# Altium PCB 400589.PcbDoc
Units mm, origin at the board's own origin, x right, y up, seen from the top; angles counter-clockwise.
Board outline 10.16 x 10.16 mm, 2 copper layers (Top Layer, Bottom Layer); 19 components, 14 nets, 51 pads, 50 vias.
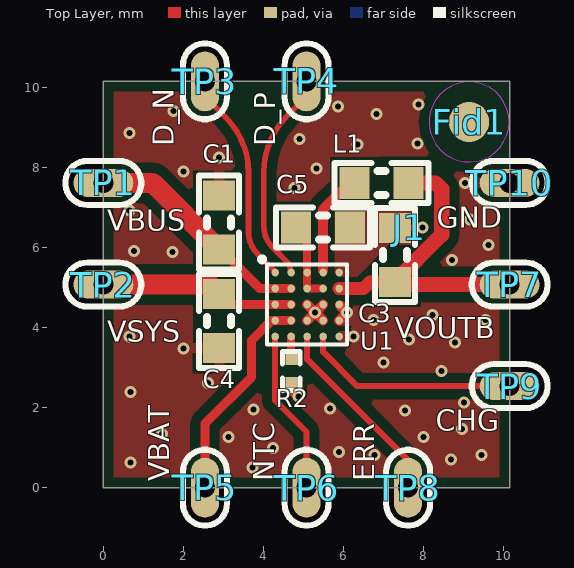
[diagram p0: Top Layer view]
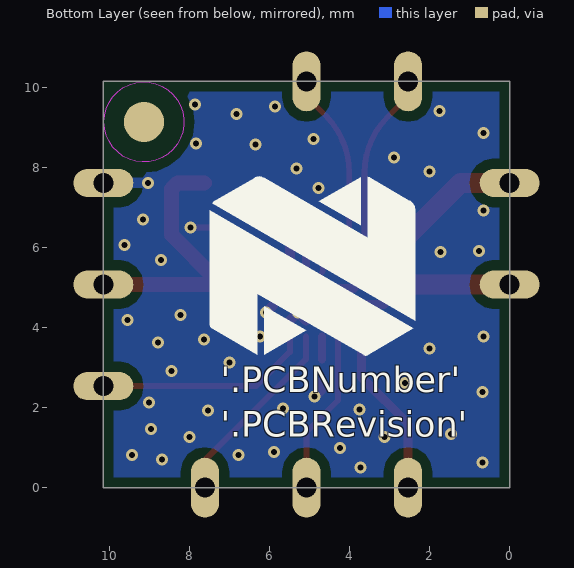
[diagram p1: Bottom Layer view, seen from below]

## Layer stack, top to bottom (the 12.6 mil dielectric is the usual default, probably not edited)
Top Solder: solder mask 0.01, Solder Resist, Dk 3.5
Top Layer: signal copper 0.036
Dielectric1: core 0.32, FR-4, Dk 4.8
Bottom Layer: signal copper 0.036
Bottom Solder: solder mask 0.01, Solder Resist, Dk 3.5

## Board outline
0,0 10.16,0 10.16,10.16 0,10.16

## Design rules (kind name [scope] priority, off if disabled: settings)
BoardOutlineClearance [All] p1: gap=0.254 ignorepadtopadclearanceinfootprint=FALSE except(0: Arc-SplitContinuation Track-SplitContinuation SMDPad-SplitContinuation THPad-SplitContinuation Via-SplitContinuation Fill-SplitContinuation Poly-SplitContinuation Region-SplitContinuation Text-SplitContinuation)
Clearance Clearance_microvia [AsMM(ViaDiameter) = 0.3 vs AsMM(ViaDiameter) = 0.3] p1: gap=0.1 ignorepadtopadclearanceinfootprint=FALSE except(0: Arc-Hole Track-Hole SMDPad-Hole THPad-Hole Via-Hole Fill-Hole Poly-Hole Region-Hole Text-Hole)
Clearance ANT_Clerance [InNet('ANT')] p2: gap=0.127 ignorepadtopadclearanceinfootprint=FALSE except(0: Arc-Hole Track-Hole SMDPad-Hole THPad-Hole Via-Hole Fill-Hole Poly-Hole Region-Hole Text-Hole)
Clearance Polygon_Clearance [(InNamedPolygon('Top_Layer-GND')) or (InNamedPolygon('Bottom_Layer-GND')) or (InNamedPolygon('Mid_Layer_1-GND')) or (InNamedPolygon('Mid_Layer_2-GND'))] p3: gap=0.254 ignorepadtopadclearanceinfootprint=FALSE except(0: Arc-Hole Track-Hole SMDPad-Hole THPad-Hole Via-Hole Fill-Hole Poly-Hole Region-Hole Text-Hole)
Clearance [All] p4: gap=0.125 ignorepadtopadclearanceinfootprint=FALSE
ComponentClearance [All] p1 off: gap=0.254 collisioncheckmode=3 verticalgap=0.254 showdistances=FALSE
DiffPairsRouting [All] p1: maxlimit=0.254 minlimit=0.241 mostfreqgap=0.241 toplayer_minwidth=0.14 toplayer_maxwidth=0.381 toplayer_prefwidth=0.14 bottomlayer_minwidth=0.14 bottomlayer_maxwidth=0.381 bottomlayer_prefwidth=0.14 maxuncoupledlength=12.7
FabricationTestPointUsage TestPointUsage [All] p1: valid=0 allowmultiple=FALSE
FabricationTestpoint Testpoint [All] p1: side=3 testpointundercomponent=TRUE minsize=1.016 maxsize=2.54 preferedsize=1.524 minholesize=0 maxholesize=1.016 preferedholesize=0.813 testpointgrid=0.025 allowsidetop=TRUE allowsidebottom=TRUE usegrid=TRUE gridtolerance=0
Height [All] p1 off: minheight=0 maxheight=25.4 prefheight=12.7
HoleSize [All] p1: absolutevalues=TRUE maxlimit=5 minlimit=0.1 maxpercent=80.000 minpercent=20.000
HoleToHoleClearance HoleToHoleClearance_L1L2 [InDrillLayerPair('Top Layer - Mid-Layer 1') vs InDrillLayerPair('Top Layer - Mid-Layer 1')] p1: gap=0.225 allowstackedmicrovias=TRUE
HoleToHoleClearance HoleToHoleClearance_L1L2_L1L3 [InDrillLayerPair('Top Layer - Mid-Layer 1') vs InDrillLayerPair('Top Layer - Mid-Layer 2')] p2: gap=0.225 allowstackedmicrovias=TRUE
HoleToHoleClearance HoleToHoleClearance_L1L3 [InDrillLayerPair('Top Layer - Mid-Layer 2') vs InDrillLayerPair('Top Layer - Mid-Layer 2')] p3: gap=0.225 allowstackedmicrovias=TRUE
HoleToHoleClearance HoleToHoleClearance_L1L3_L3L4 [InDrillLayerPair('Top Layer - Mid-Layer 2') vs InDrillLayerPair('Mid-Layer 2 - Mid-Layer 3')] p4: gap=0.225 allowstackedmicrovias=TRUE
HoleToHoleClearance HoleToHoleClearance_L3L4 [InDrillLayerPair('Mid-Layer 2 - Mid-Layer 3') vs InDrillLayerPair('Mid-Layer 2 - Mid-Layer 3')] p5: gap=0.225 allowstackedmicrovias=TRUE
HoleToHoleClearance HoleToHoleClearance_L3L4_L4L6 [InDrillLayerPair('Mid-Layer 2 - Mid-Layer 3') vs InDrillLayerPair('Mid-Layer 3 - Bottom Layer')] p6: gap=0.225 allowstackedmicrovias=TRUE
HoleToHoleClearance HoleToHoleClearance_L4L6 [InDrillLayerPair('Mid-Layer 3 - Bottom Layer') vs InDrillLayerPair('Mid-Layer 3 - Bottom Layer')] p7: gap=0.225 allowstackedmicrovias=TRUE
HoleToHoleClearance HoleToHoleClearance_L1L2_L1L6 [InDrillLayerPair('Top Layer - Mid-Layer 1') vs InDrillLayerPair('Top Layer - Bottom Layer')] p8: gap=0.275 allowstackedmicrovias=FALSE
HoleToHoleClearance HoleToHoleClearance_L1L3_L1L6 [InDrillLayerPair('Top Layer - Mid-Layer 2') vs InDrillLayerPair('Top Layer - Bottom Layer')] p9: gap=0.275 allowstackedmicrovias=FALSE
HoleToHoleClearance HoleToHoleClearance_L3L4_L1L6 [InDrillLayerPair('Mid-Layer 2 - Mid-Layer 3') vs InDrillLayerPair('Top Layer - Bottom Layer')] p10: gap=0.275 allowstackedmicrovias=FALSE
HoleToHoleClearance HoleToHoleClearance_L4L6_L1L6 [InDrillLayerPair('Mid-Layer 3 - Bottom Layer') vs InDrillLayerPair('Top Layer - Bottom Layer')] p11: gap=0.275 allowstackedmicrovias=FALSE
HoleToHoleClearance HoleToHoleClearance_L1L6 [InDrillLayerPair('Top Layer - Bottom Layer') vs InDrillLayerPair('Top Layer - Bottom Layer')] p12: gap=0.45 allowstackedmicrovias=FALSE
MinimumAnnularRing [All] p1 off: minimumring=0.152
PolygonConnect PolygonConnect_1 [isVia and innet(gnd) or InNet('PVSS')] p1: connectstyle=Direct reliefconductorwidth=0.254 reliefentries=4 polygonreliefangle="90 Angle" airgapwidth=0.254
PolygonConnect [All] p2: connectstyle=Relief reliefconductorwidth=0.254 reliefentries=4 polygonreliefangle="90 Angle" airgapwidth=0.254
RoutingVias [All] p1: holewidth=0.305 width=0.61 viastyle="Through Hole" minholewidth=0.1 minwidth=0.3 maxholewidth=0.711 maxwidth=1.27 useviatemplates=TRUE viatemplateguid#1={46AA5E60-8EE7-483D-A1B2-04B1209392C7} viatemplatename#1=v30h15m0mx0
SilkToSolderMaskClearance SilkscreenOverComponentPads [IsPad] p1: minsilkscreentomaskgap=0.254 clearancetoexposedcopper=TRUE
SolderMaskExpansion [IsVia] p1: expansion=0.076 istentingtop=TRUE
Width [All] p1: maxlimit=0.508 minlimit=0.15 preferedwidth=0.305 minimp=50.000000 maximp=50.000000 favimp=50.000000
22 further rules are at their usual default settings.

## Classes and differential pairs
differential pair class USB: D
differential pair D: +D_P -D_N

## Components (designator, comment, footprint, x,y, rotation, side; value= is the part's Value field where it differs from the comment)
C1 "2.2µF" CAPC1608X06L 2.896,6.629 r270 top
C3 "10µF" CAPC1608X06L 7.29,5.817 r270 top
C4 "10µF" CAPC1608X06L 2.896,4.166 r90 top
C5 "10µF" CAPC1608X06L 5.496,6.502 r180 top
Fid1 "Fiducial mark" Fiducial 9.144,9.144 r0 top
J1 "N.A." "2 PIN STARPOINT" 7.645,6.502 r180 top net-tie
L1 "2.2µH" INDC1608X06L 6.96,7.62 r0 top
R2 "0R" RESC0603X03L_C 4.699,2.921 r90 top
TP1 "TP" "TESTPAD-TH - 0.5mm" 0,7.62 r90 top
TP2 "TP" "TESTPAD-TH - 0.5mm" 0,5.08 r90 top
TP3 "TP" "TESTPAD-TH - 0.5mm" 2.54,10.16 r0 top
TP4 "TP" "TESTPAD-TH - 0.5mm" 5.08,10.16 r0 top
TP5 "TP" "TESTPAD-TH - 0.5mm" 2.54,0 r0 top
TP6 "TP" "TESTPAD-TH - 0.5mm" 5.08,0 r0 top
TP7 "TP" "TESTPAD-TH - 0.5mm" 10.16,5.08 r270 top
TP8 "TP" "TESTPAD-TH - 0.5mm" 7.62,0 r0 top
TP9 "TP" "TESTPAD-TH - 0.5mm" 10.16,2.54 r90 top
TP10 "TP" "TESTPAD-TH - 0.5mm" 10.16,7.62 r90 top
U1 "nPM1100-CAAAC0" BGA25C40P5X5_200X200X50 5.096,4.58 r0 top locked

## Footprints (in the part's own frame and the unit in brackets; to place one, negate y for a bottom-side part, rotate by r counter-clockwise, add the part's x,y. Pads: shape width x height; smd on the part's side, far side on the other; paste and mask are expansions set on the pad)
"2 PIN STARPOINT" [mil]
  round 5.98 smd paste-196.85 mask-196.85: 1(8,0) 2(-8,0)
  Top Layer region: -11,-3 11,-3 11,3 -11,3
BGA25C40P5X5_200X200X50 [mm] "BGA, 25-Leads, Body 2.00x2.00mmx0.50mm, Pitch 0.40mm"
  round 0.193 smd mask+0.075: A1(-0.8,0.8) A2(-0.4,0.8) A3(0,0.8) A4(0.4,0.8) A5(0.8,0.8) B1(-0.8,0.4) B2(-0.4,0.4) B3(0,0.4) B4(0.4,0.4) B5(0.8,0.4) C1(-0.8,0) C2(-0.4,0) C3(0,0) C4(0.4,0) C5(0.8,0) D1(-0.8,-0.4) D2(-0.4,-0.4) D3(0,-0.4) D4(0.4,-0.4) D5(0.8,-0.4) E1(-0.8,-0.8) E2(-0.4,-0.8) E3(0,-0.8) E4(0.4,-0.8) E5(0.8,-0.8)
  silkscreen extent -1.18,-1 1,1.18, body extent -1,-1 1,1, height 0.5
CAPC1608X06L [mm] "Chip Capacitor, 2-Leads, Body 1.6x0.8mm, IPC High Density"
  rect 0.75x0.8 smd: 1(-0.675,0) 2(0.675,0)
  silkscreen extent -1.17,-0.5 1.17,0.5, body extent -0.8,-0.43 0.8,0.43, height 0.8
Fiducial [mm] "Fiducial Mark"
  round 1 smd paste-1 mask+0.5: 0(0,0)
  round 1 smd far side paste-1 mask+0.5: 0(0,0)
  Top Layer keep-out circle w0.01: c0,0 r1
  Bottom Layer keep-out circle w0.01: c0,0 r1
INDC1608X06L [mm] "Chip Inductor, 2-Leads, Body 1.6x0.8mm, IPC High Density"
  rect 0.75x0.8 smd: 1(-0.675,0) 2(0.675,0)
  silkscreen extent -1.17,-0.5 1.17,0.5, body extent -0.8,-0.48 0.8,0.48, height 0.8
RESC0603X03L_C [mm] "Chip Resistor, 2-Leads, Body 0.6x0.3mm, IPC High Density"
  rect 0.27x0.3 smd: 1(-0.285,0) 2(0.285,0)
  silkscreen extent -0.49,-0.22 0.49,0.22, body extent -0.3,-0.15 0.3,0.15, height 0.23
"TESTPAD-TH - 0.5mm" [mm]
  oval 0.7x1.5 hole 0.5: 1(0,0)
  silkscreen extent -0.55,-0.95 0.55,0.95

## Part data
C1: library part C0603-2µ2-25V-X5R, "Capacitor, Ceramic, X5R, ±10%, 25V", Manufacturer=Murata, Manufacturer Part Number=GRM188R61E225KA12D, Part number IPS=N.A., Supplier Part Number 1=490-10731-1-ND
C3 C4 C5: library part 0603-10u-10V-X7T-GRM188, "CAP CER 10UF 10V X7T 0603", Manufacturer=Murata, Manufacturer Part Number=GRM188D71A106MA73, Part number IPS=00000004696, Supplier Part Number 1=490-7200-1-ND
Fid1: library part Fid-Mark, "Fiducial Mark", Part number IPS=N.A.
J1: library part "2 pin starpoint", "Starpoint"
L1: library part BRL1608T2R2M, "FIXED IND 2.2UH 500MA 520 MOHM", Manufacturer="Taiyo Yuden", Part number IPS=N.A., Supplier Part Number 1=587-2899-1-ND
R2: library part R0201-0R, "Resistor, ±5%, 0.05W", Manufacturer=N.A., Part number IPS=00000003245
TP1 TP2 TP3 TP4 TP5 TP6 TP7 TP8 TP9 TP10: library part "Testpoint TH 0.5mm", "Testpoint, through hole", Manufacturer=N.A.
U1: "Li-Ion/Li-Polymer USB battery charger with a high efficiency buck regulator", Manufacturer="Nordic Semiconductor", Part number IPS=N.A.

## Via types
v1: diameter 0.3/0.3 (per signal layer), hole 0.15, Top Layer to Bottom Layer, tented both sides, 46 vias
v2: diameter 0.3, hole 0.15, Top Layer to Bottom Layer, tented both sides, 4 vias

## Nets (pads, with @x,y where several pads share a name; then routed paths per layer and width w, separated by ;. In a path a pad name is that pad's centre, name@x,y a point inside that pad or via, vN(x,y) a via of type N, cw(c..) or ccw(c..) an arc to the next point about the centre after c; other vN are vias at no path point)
CHG: TP9.1 U1.E4 | length 5.4
  Top Layer w0.152: U1.E4 5.496,3.394 6.35,2.54 TP9.1
D_N: TP3.1 U1.A1 | length 5.4
  Top Layer w0.14: TP3.1 2.54,9.779 3.054,9.265 cw(c1.663,7.874) 3.63,7.874 3.63,6.388 ccw(c4.404,6.388) 3.857,5.84 4.281,5.417 cw(c4.243,5.38) U1.A1
D_P: TP4.1 U1.A2 | length 5.4
  Top Layer w0.14: U1.A2 cw(c4.742,5.426) 4.677,5.426 4.677,5.479 ccw(c4.483,5.479) 4.62,5.616 4.238,5.998 cw(c4.785,6.545) 4.011,6.545 4.011,7.874 cw(c6.03,7.874) 4.603,9.302 5.08,9.779 TP4.1
DEC: C5.2 U1.A3 U1.B3 U1.B4 | length 2.2
  Top Layer w0.2: C5.2@4.821,6.68 5.096,6.405 U1.A3 U1.B3 U1.B4
ERR: TP8.1 U1.E3 | length 4.8
  Top Layer w0.15: U1.E3 5.096,3.21 7.62,0.686 TP8.1
GND: C1.1 C4.1 J1.2 R2.1 TP10.1 U1.C3 U1.C4 U1.C5 U1.D3 U1.D4 U1.D5 U1.E5 | length 2.1
  Top Layer w0.254: R2.1 4.699,2.464 v1(4.877,2.286) ; U1.D3 v2(5.296,4.38) ; U1.C3 v2(5.296,4.38) ; U1.D4 v2(5.296,4.38) ; U1.C4 v2(5.296,4.38) ; U1.D5 v2(6.096,4.38) U1.C5@5.924,4.552
  other v1: 3.734,0.508 0.686,0.635 8.687,0.711 6.782,0.813 9.449,0.813 5.893,0.889 4.242,0.991 3.124,1.27 8.001,1.27 1.473,1.346 8.966,1.473 7.544,1.93 3.759,1.956 5.664,1.981 9.017,2.134 0.686,2.388 2.616,2.616 8.458,2.921 7.01,3.124 2.007,3.48 8.788,3.632 7.645,3.708 0.66,3.785 6.756,4.191 9.55,4.191 8.23,4.318 8.712,5.69 1.727,5.893 0.762,5.918 9.627,6.071 9.169,6.706 0.66,6.934 4.775,7.493 9.042,7.62 2.007,7.899 5.334,7.976 2.896,8.255 6.35,8.585 7.849,8.611 4.902,8.712 0.66,8.865 6.833,9.347 1.753,9.423 5.867,9.525 7.874,9.576
  other v2: 6.248,3.785 7.976,6.502
ICHG: R2.2 U1.E2 | length 0.6
  Top Layer w0.203: R2.2@4.696,3.206 U1.E2
NetL1_1: L1.1 U1.A4 | length 2.6
  Top Layer w0.25: U1.A4@5.496,5.43 5.496,6.96 6.156,7.62 L1.1
NTC: TP6.1 U1.E1 | length 4.1
  Top Layer w0.15: U1.E1 4.296,2.181 5.08,1.397 TP6.1
PVSS: C3.1 C5.1 J1.1 U1.A5
VBAT: TP5.1 U1.D1 U1.D2 | length 5.4
  Top Layer w0.229: TP5.1 2.54,1.6 3.708,2.769 3.708,3.683 4.205,4.18 U1.D1 U1.D2
VBUS: C1.2 TP1.1 U1.B1 U1.B2 | length 5.8
  Top Layer w0.229: C1.2 2.936,5.954 3.91,4.98 U1.B1 U1.B2
  Top Layer w0.508: TP1.1 1.23,7.62 C1.2
VOUTB: C3.2 L1.2 TP7.1 U1.B5 | length 8.1
  Top Layer w0.33: U1.B5 6.504,4.98 6.666,5.142 C3.2
  Top Layer w0.381: L1.2 8.306,7.62 8.458,7.468 8.458,6.325 7.29,5.156 C3.2 7.351,5.08 TP7.1
VSYS: C4.2 TP2.1 U1.C1 U1.C2 | length 4.9
  Top Layer w0.229: C4.2 3.156,4.58 U1.C1 U1.C2
  Top Layer w0.508: TP2.1 2.656,5.08 C4.2
pads on no net: Fid1.0

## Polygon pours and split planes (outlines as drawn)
GND on Top Layer "Top_Layer-GND" (solid, remove dead copper, pour order 14): 0,0 0,10.16 10.16,10.16 10.16,0
PVSS on Top Layer "PVSS_L01_P013" (solid, pour order 13): 5.791,5.258 5.791,6.909 7.696,6.909 7.696,6.071 7.137,6.071 6.325,5.258
GND on Bottom Layer "Bottom_Layer-GND" (solid, remove dead copper, pour order 11): 0,0 0,10.16 10.16,10.16 10.16,0

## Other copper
Top Layer:
  pour cut-out: 6.22,8.153 7.571,8.153 7.571,7.061 6.221,7.061
  pour cut-out: 7.722,6.909 7.722,6.109 8.179,6.109 8.179,6.909

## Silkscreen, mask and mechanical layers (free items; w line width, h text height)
Top Overlay:
  text "D_N" at 1.93,8.534 h0.89 r90
  text "D_P" at 4.469,8.534 h0.89 r90
  text "GND" at 8.331,6.325 h0.89
  text "VBUS" at 0.102,6.248 h0.89
  text "VOUTB" at 7.29,3.556 h0.89
  text "VSYS" at 0.102,3.48 h0.89
  text "CHG" at 8.306,1.245 h0.89
  text "VBAT" at 1.829,0.167 h0.89 r90
  text "NTC" at 4.453,0.167 h0.89 r90
  text "ERR" at 6.949,0.167 h0.89 r90
Bottom Overlay:
  region: 7.499,4.102 7.499,6.931 2.407,3.991 3.534,3.328 3.546,3.321 3.554,3.317 3.562,3.314 3.571,3.31 3.582,3.307 3.59,3.305 3.595,3.304 3.601,3.304 3.612,3.305 3.618,3.306 3.627,3.309 3.637,3.313 3.645,3.317 3.651,3.319 6.316,4.854 6.315,3.323 7.42,3.968 7.443,3.983 7.457,3.996 7.468,4.01 7.481,4.027 7.49,4.049 7.495,4.067 7.499,4.088
  region: 6.135,3.328 6.135,4.541 5.085,3.935
  region: 4.774,7.167 3.724,6.557 3.724,7.768
  region: 7.44,7.106 2.36,4.173 2.36,6.932 2.361,6.956 2.364,6.979 2.369,7.005 2.378,7.035 2.395,7.07 2.414,7.1 2.445,7.135 2.465,7.153 2.489,7.171 2.506,7.18 3.489,7.75 3.501,7.756 3.523,7.765 3.543,7.773 3.543,6.244 6.136,7.743 6.158,7.755 6.18,7.765 6.195,7.77 6.217,7.776 6.233,7.779 6.249,7.78 6.266,7.781 6.28,7.78 6.291,7.778 6.309,7.775 6.323,7.771 6.345,7.763 6.357,7.758 6.373,7.751 6.391,7.742 7.351,7.183 7.374,7.169 7.394,7.155 7.407,7.143 7.42,7.13 7.434,7.114
  text "'.PCBNumber'" at 7.223,2.388 h0.64
  text "'.PCBRevision'" at 7.223,1.273 h0.64
Board Outline:
  the board outline again, w0.152

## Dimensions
0,0 to 10.16,0 on Dimension
0,10.16 to 0,0 on Dimension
